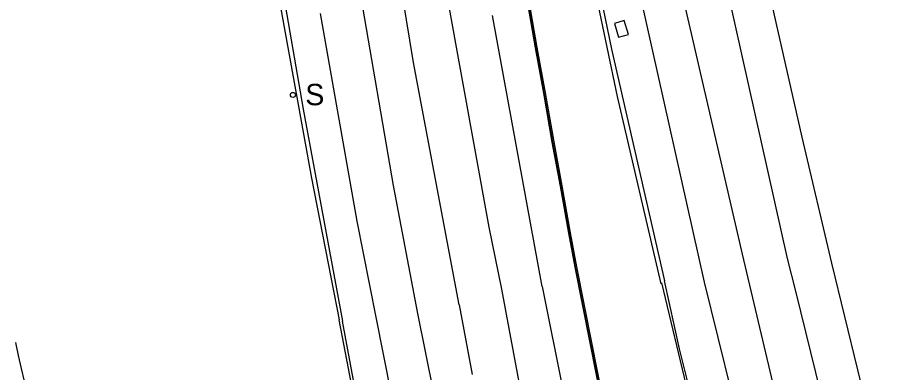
# Model space of a CAD drawing. Extents: x 368532 to 392481, y 10654822 to 10676899.
# Drawn here: x 375822.6 to 376068.9, y 10666727.9 to 10666827.5 of the extents above; entities that cross this region are included whole.
import ezdxf

# ---------------------------------------------------------------- set-up
doc = ezdxf.new("R2010")
doc.units = 0
for name, color, linetype in [('p_Catenary', 7, 'Continuous'), ('p_drainage inlet', 7, 'Continuous'), ('p_road - paved curb', 7, 'Continuous'), ('p_road guard rails', 7, 'Continuous'), ('p_road paint stripe', 7, 'Continuous'), ('p_structure sign', 7, 'Continuous')]:
    doc.layers.add(name, color=color, linetype=linetype)

msp = doc.modelspace()

# ---------------------------------------------------------------- linework, layer by layer
at = {"layer": 'p_Catenary'}
msp.add_lwpolyline([(375821.98, 10666736.35), (375822.79, 10666732.7), (375823.6, 10666729.05), (375824.41, 10666725.41), (375825.23, 10666721.76), (375826.04, 10666718.11), (375826.85, 10666714.47), (375827.67, 10666710.82), (375828.48, 10666707.17), (375829.29, 10666703.53), (375830.11, 10666699.88), (375830.92, 10666696.23), (375831.73, 10666692.59), (375832.54, 10666688.94), (375833.36, 10666685.29), (375834.17, 10666681.65), (375834.98, 10666678), (375835.8, 10666674.35), (375836.61, 10666670.71), (375837.42, 10666667.06), (375838.24, 10666663.41), (375839.05, 10666659.77), (375839.86, 10666656.12)], dxfattribs=at)
at = {"layer": 'p_drainage inlet'}
for p, q in [((375992.65, 10666826.66), (375989.92, 10666825.84)), ((375993.82, 10666822.77), (375992.65, 10666826.66)), ((375989.92, 10666825.84), (375991.08, 10666821.96)), ((375991.08, 10666821.96), (375993.82, 10666822.77))]:
    msp.add_line(p, q, dxfattribs=at)
at = {"layer": 'p_road - paved curb'}
for p, q in [((375976.91, 10666877.62), (375989.12, 10666818.59)), ((375893.11, 10666856.75), (375902.64, 10666801.76)), ((375967.77, 10666819.05), (375965.6, 10666831.42)), ((375967.92, 10666819.08), (375965.75, 10666831.45)), ((375968.26, 10666819.14), (375966.09, 10666831.51)), ((375970.07, 10666806.28), (375967.77, 10666819.05)), ((375970.22, 10666806.31), (375967.92, 10666819.08)), ((375970.56, 10666806.37), (375968.26, 10666819.14)), ((375989.12, 10666818.59), (376003.94, 10666753.64)), ((375972.48, 10666792.49), (375970.07, 10666806.28)), ((375972.63, 10666792.52), (375970.22, 10666806.31)), ((375972.97, 10666792.58), (375970.56, 10666806.37)), ((375902.64, 10666801.76), (375909.6, 10666764.43)), ((375974.75, 10666780.21), (375972.48, 10666792.49)), ((375974.9, 10666780.24), (375972.63, 10666792.52)), ((375975.24, 10666780.3), (375972.97, 10666792.58)), ((375977.12, 10666766.98), (375974.75, 10666780.21)), ((375977.27, 10666767.01), (375974.9, 10666780.24)), ((375977.61, 10666767.07), (375975.24, 10666780.3)), ((375979.03, 10666757.45), (375977.27, 10666767.01)), ((375979.37, 10666757.51), (375977.61, 10666767.07)), ((375978.88, 10666757.42), (375977.12, 10666766.98)), ((375909.6, 10666764.43), (375913.65, 10666742.33)), ((375983.07, 10666736.18), (375978.88, 10666757.42)), ((375983.22, 10666736.21), (375979.03, 10666757.45)), ((375983.56, 10666736.28), (375979.37, 10666757.51)), ((376008.18, 10666734.53), (376003.94, 10666753.64)), ((375921.14, 10666702.64), (375913.65, 10666742.33)), ((375984.68, 10666728.18), (375983.07, 10666736.18)), ((375984.83, 10666728.21), (375983.22, 10666736.21)), ((375985.17, 10666728.28), (375983.56, 10666736.28)), ((376017.46, 10666697.11), (376008.18, 10666734.53)), ((375986.03, 10666721.36), (375984.68, 10666728.18)), ((375986.18, 10666721.39), (375984.83, 10666728.21)), ((375986.52, 10666721.46), (375985.17, 10666728.28))]:
    msp.add_line(p, q, dxfattribs=at)
at = {"layer": 'p_road guard rails'}
for p, q in [((375975.74, 10666876.71), (375990.71, 10666805.35)), ((375896.04, 10666832.04), (375904.99, 10666782.39)), ((375990.71, 10666805.35), (376002.87, 10666752.81)), ((375904.99, 10666782.39), (375912.7, 10666742.65)), ((376003.06, 10666753.08), (376011.33, 10666718.82)), ((375918.66, 10666712.25), (375912.7, 10666742.65))]:
    msp.add_line(p, q, dxfattribs=at)
at = {"layer": 'p_road paint stripe'}
for p, q in [((375933.62, 10666814.9), (375920.56, 10666893.3)), ((376038.42, 10666759.88), (376011.77, 10666879.22)), ((375989.89, 10666866.03), (376015.07, 10666753.28)), ((375914.52, 10666858.4), (375927.9, 10666780.39)), ((375940.72, 10666846.11), (375954.66, 10666768.65)), ((376033.28, 10666834.41), (376042.44, 10666793.98)), ((376009.01, 10666833.43), (376025.7, 10666761.09)), ((375907.43, 10666828.61), (375917.73, 10666770.35)), ((375969.67, 10666752.02), (375955.75, 10666828.09)), ((375946.4, 10666746.87), (375933.62, 10666814.9)), ((376042.44, 10666793.98), (376050.7, 10666758.57)), ((375927.9, 10666780.39), (375934.7, 10666744.44)), ((375917.73, 10666770.35), (375923.01, 10666743.43)), ((375954.66, 10666768.65), (375958.25, 10666751.23)), ((376025.7, 10666761.09), (376034.63, 10666723.16)), ((376040.71, 10666750.75), (376038.42, 10666759.88)), ((376050.7, 10666758.57), (376058.05, 10666728.59)), ((376015.07, 10666753.28), (376023.86, 10666717.6)), ((375958.25, 10666751.23), (375963.79, 10666721.78)), ((375969.67, 10666752.02), (375976.45, 10666718.34)), ((376058.56, 10666678.62), (376040.71, 10666750.75)), ((375946.4, 10666746.87), (375949.98, 10666727.35)), ((375923.01, 10666743.43), (375930.03, 10666708.45)), ((375934.7, 10666744.44), (375942.2, 10666707.16)), ((376058.05, 10666728.59), (376068.94, 10666684.94))]:
    msp.add_line(p, q, dxfattribs=at)
at = {"layer": 'p_structure sign'}
msp.add_circle((375899.79, 10666805.79), 0.713, dxfattribs=at)

# ---------------------------------------------------------------- texts
msp.add_text('S', height=6, dxfattribs=at).set_placement((375903.24, 10666802.9))

doc.saveas('drawing.dxf')
